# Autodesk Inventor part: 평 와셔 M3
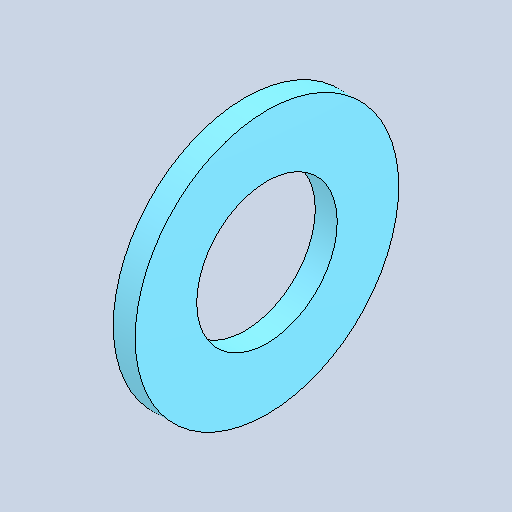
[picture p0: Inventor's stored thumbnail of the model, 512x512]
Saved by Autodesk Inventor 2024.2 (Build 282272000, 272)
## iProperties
Created: 2025-09
Part Number: 평 와셔 M3
Material: 강철, 연강
Description: 평면 와셔
Document SubType Name: Modeling
Designer: home
Density: 7.85 g/cm^3
Appearance: 기본값
Author: jhkim
Sending System: Autodesk Inventor 2026
Preprocessor: ST-DEVELOPER v20.1
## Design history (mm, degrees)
feature "Solid1"
node "솔리드1"
